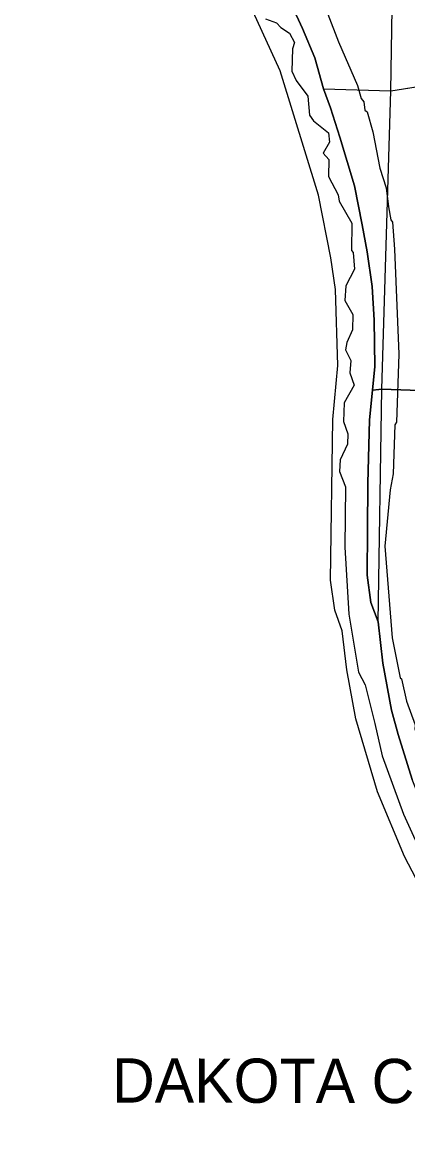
# Model space of a CAD drawing. Extents: x -157.2 to -99.3, y 12.2 to 46.2.
# Drawn here: x -147.848 to -146.803, y 21.191 to 24.227 of the extents above; entities that cross this region are included whole.
import ezdxf

# ---------------------------------------------------------------- set-up
doc = ezdxf.new("R2010")
doc.units = 0
for name, color, linetype in [('tdCoClipBndry', 7, 'Continuous'), ('tdCoCoBndry', 7, 'Continuous'), ('tdCoCoBndryTxt', 7, 'Continuous'), ('tdCoHydroRiver', 7, 'Continuous'), ('tdCoSectLine', 7, 'Continuous'), ('tdCoSectLinePart', 7, 'Continuous'), ('tdCoStBndry', 7, 'Continuous'), ('tdCoStBndryPart', 7, 'Continuous'), ('tdCoTwpBndry', 7, 'Continuous'), ('tdCoTwpBndryShd', 7, 'Continuous')]:
    doc.layers.add(name, color=color, linetype=linetype)

msp = doc.modelspace()

# ---------------------------------------------------------------- linework, layer by layer
at = {"layer": 'tdCoClipBndry'}
msp.add_lwpolyline([(-145.817, 21.0314), (-146.2268, 21.2848), (-146.2839, 21.3266), (-146.4611, 21.4845), (-146.5453, 21.5662), (-146.6561, 21.702), (-146.7589, 21.8639), (-146.8111, 21.9641), (-146.8849, 22.1401), (-146.9435, 22.3377), (-146.9681, 22.4706), (-146.9803, 22.5766), (-147.0007, 22.6324), (-147.0119, 22.7144), (-147.0061, 23.1502), (-146.9918, 23.2968), (-146.9986, 23.5021), (-147.0107, 23.5882), (-147.0443, 23.7589), (-147.1482, 24.0956), (-147.2706, 24.3631)], dxfattribs=at)
at = {"layer": 'tdCoCoBndry'}
msp.add_lwpolyline([(-146.7907, 22.1736), (-146.8285, 22.2952), (-146.8463, 22.3609), (-146.8697, 22.4886), (-146.8825, 22.6008), (-146.903, 22.6534), (-146.9127, 22.7275), (-146.9118, 22.8503), (-146.9109, 22.9761), (-146.9061, 23.1487), (-146.8977, 23.2298), (-146.8917, 23.2934), (-146.8931, 23.4198), (-146.8988, 23.5107), (-146.9121, 23.6048), (-146.9265, 23.6779), (-146.9472, 23.7834), (-146.9864, 23.9154), (-147.012, 23.9956), (-147.0312, 24.0467), (-147.0546, 24.1312), (-147.088, 24.2108), (-147.1491, 24.3442)], dxfattribs=at)
at = {"layer": 'tdCoHydroRiver'}
for points in [[(-147.201, 24.5448), (-147.1535, 24.4833), (-147.0579, 24.3191), (-147.0192, 24.2499), (-146.9901, 24.1747), (-146.9387, 24.0561), (-146.9288, 24.021), (-146.9212, 24.0113), (-146.9188, 23.9891), (-146.9126, 23.9842), (-146.8971, 23.93), (-146.8782, 23.8314), (-146.861, 23.7787), (-146.8548, 23.7264), (-146.8481, 23.6914), (-146.8435, 23.685), (-146.838, 23.6122), (-146.8269, 23.3275), (-146.8329, 23.1429)], [(-147.1885, 24.2365), (-147.1588, 24.2261), (-147.1466, 24.213), (-147.1235, 24.1981), (-147.1101, 24.1724), (-147.1154, 24.1552), (-147.1174, 24.0952), (-147.1056, 24.0695), (-147.0738, 24.0274), (-147.0692, 23.9752), (-147.0586, 23.9606), (-147.0171, 23.9276), (-147.0148, 23.9023), (-147.0315, 23.8728), (-147.0163, 23.855), (-147.0178, 23.8092), (-146.9911, 23.7594), (-146.9885, 23.7419), (-146.9541, 23.6823), (-146.955, 23.6081), (-146.9504, 23.6032), (-146.9472, 23.5573), (-146.9708, 23.5123), (-146.9736, 23.4729), (-146.9512, 23.4343), (-146.9526, 23.3933), (-146.9679, 23.359), (-146.9717, 23.3386), (-146.9569, 23.3097), (-146.9596, 23.2766), (-146.948, 23.2431), (-146.9749, 23.195), (-146.9765, 23.1445), (-146.965, 23.111), (-146.9659, 23.0826), (-146.9862, 23.0406), (-146.9873, 23.0091), (-146.9713, 22.9675), (-146.9735, 22.8033), (-146.9621, 22.6213), (-146.9357, 22.4641)], [(-146.8329, 23.1429), (-146.8379, 23.1352), (-146.8423, 23.0027), (-146.85, 22.9587), (-146.8645, 22.806), (-146.8443, 22.5574), (-146.8226, 22.4493), (-146.8195, 22.446), (-146.8057, 22.3855), (-146.7826, 22.3216), (-146.783, 22.309), (-146.7784, 22.3057), (-146.7672, 22.2595), (-146.6163, 21.9544), (-146.5789, 21.8916), (-146.3915, 21.6358), (-146.3473, 21.5886), (-146.2967, 21.5427), (-146.252, 21.5096), (-146.0694, 21.3504), (-145.7018, 21.1044)], [(-146.9357, 22.4641), (-146.9179, 22.4303), (-146.8914, 22.3252), (-146.8721, 22.2377), (-146.8142, 22.0794), (-146.7494, 21.9383), (-146.6351, 21.764), (-146.5515, 21.6664), (-146.347, 21.4527), (-146.2458, 21.3641), (-146.1025, 21.2583), (-145.8594, 21.1128)]]:
    msp.add_lwpolyline(points, dxfattribs=at)
at = {"layer": 'tdCoSectLine'}
for points in [[(-147.8482, 25.1108), (-147.7708, 25.0498), (-147.7104, 25.0029), (-147.6266, 24.9312), (-147.547, 24.8525), (-147.4738, 24.7758), (-147.3843, 24.6807), (-147.3254, 24.6126), (-147.2877, 24.5643), (-147.2238, 24.4756), (-147.1825, 24.411), (-147.1491, 24.3442), (-147.088, 24.2108), (-147.0546, 24.1312), (-147.0312, 24.0467)], [(-146.8481, 24.0419), (-146.8319, 25.0427)], [(-146.8481, 24.0419), (-145.853, 24.1993)], [(-147.0312, 24.0467), (-146.8481, 24.0419)], [(-147.0312, 24.0467), (-147.012, 23.9956), (-146.9864, 23.9154), (-146.9472, 23.7834), (-146.9265, 23.6779), (-146.9121, 23.6048), (-146.8988, 23.5107), (-146.8931, 23.4198), (-146.8917, 23.2934), (-146.8977, 23.2298)], [(-146.8729, 23.2324), (-146.8481, 24.0419)], [(-146.8977, 23.2298), (-146.9061, 23.1487), (-146.9109, 22.9761), (-146.9118, 22.8503), (-146.9127, 22.7275), (-146.903, 22.6534), (-146.8825, 22.6008)], [(-146.8977, 23.2298), (-146.8729, 23.2324)], [(-146.8825, 22.6008), (-146.8729, 23.2324)], [(-146.8729, 23.2324), (-145.8715, 23.197)], [(-146.8825, 22.6008), (-146.8697, 22.4886), (-146.8463, 22.3609), (-146.8285, 22.2952), (-146.7907, 22.1736)]]:
    msp.add_lwpolyline(points, dxfattribs=at)
at = {"layer": 'tdCoSectLinePart'}
for points in [[(-147.8482, 25.1108), (-147.7708, 25.0498), (-147.7104, 25.0029), (-147.6266, 24.9312), (-147.547, 24.8525), (-147.4738, 24.7758), (-147.3843, 24.6807), (-147.3254, 24.6126), (-147.2877, 24.5643), (-147.2238, 24.4756), (-147.1825, 24.411), (-147.1491, 24.3442), (-147.088, 24.2108), (-147.0546, 24.1312), (-147.0312, 24.0467)], [(-146.8481, 24.0419), (-146.8319, 25.0427)], [(-146.8481, 24.0419), (-146.3861, 24.115)], [(-147.0312, 24.0467), (-146.8481, 24.0419)], [(-147.0312, 24.0467), (-147.012, 23.9956), (-146.9864, 23.9154), (-146.9472, 23.7834), (-146.9265, 23.6779), (-146.9121, 23.6048), (-146.8988, 23.5107), (-146.8931, 23.4198), (-146.8917, 23.2934), (-146.8977, 23.2298)], [(-146.8729, 23.2324), (-146.8481, 24.0419)], [(-146.8977, 23.2298), (-146.9061, 23.1487), (-146.9109, 22.9761), (-146.9118, 22.8503), (-146.9127, 22.7275), (-146.903, 22.6534), (-146.8825, 22.6008)], [(-146.8977, 23.2298), (-146.8729, 23.2324)], [(-146.8825, 22.6008), (-146.8729, 23.2324)], [(-146.8729, 23.2324), (-145.8715, 23.197)], [(-146.8825, 22.6008), (-146.8697, 22.4886), (-146.8463, 22.3609), (-146.8285, 22.2952), (-146.7907, 22.1736)]]:
    msp.add_lwpolyline(points, dxfattribs=at)
at = {"layer": 'tdCoStBndry'}
msp.add_lwpolyline([(-147.1491, 24.3442), (-147.088, 24.2108), (-147.0546, 24.1312), (-147.0312, 24.0467), (-147.012, 23.9956), (-146.9864, 23.9154), (-146.9472, 23.7834), (-146.9265, 23.6779), (-146.9121, 23.6048), (-146.8988, 23.5107), (-146.8931, 23.4198), (-146.8917, 23.2934), (-146.8977, 23.2298), (-146.9061, 23.1487), (-146.9109, 22.9761), (-146.9118, 22.8503), (-146.9127, 22.7275), (-146.903, 22.6534), (-146.8825, 22.6008), (-146.8697, 22.4886), (-146.8463, 22.3609), (-146.8285, 22.2952), (-146.7907, 22.1736)], dxfattribs=at)
at = {"layer": 'tdCoStBndryPart'}
msp.add_lwpolyline([(-147.1491, 24.3442), (-147.088, 24.2108), (-147.0546, 24.1312), (-147.0312, 24.0467), (-147.012, 23.9956), (-146.9864, 23.9154), (-146.9472, 23.7834), (-146.9265, 23.6779), (-146.9121, 23.6048), (-146.8988, 23.5107), (-146.8931, 23.4198), (-146.8917, 23.2934), (-146.8977, 23.2298), (-146.9061, 23.1487), (-146.9109, 22.9761), (-146.9118, 22.8503), (-146.9127, 22.7275), (-146.903, 22.6534), (-146.8825, 22.6008), (-146.8697, 22.4886), (-146.8463, 22.3609), (-146.8285, 22.2952), (-146.7907, 22.1736)], dxfattribs=at)
at = {"layer": 'tdCoTwpBndry'}
msp.add_lwpolyline([(-145.8183, 23.1948), (-145.8715, 23.197), (-146.8729, 23.2324), (-146.8972, 23.2298)], dxfattribs=at)
at = {"layer": 'tdCoTwpBndryShd'}
for points in [[(-146.8825, 22.6008), (-146.903, 22.6534), (-146.9127, 22.7275), (-146.9118, 22.8503), (-146.9109, 22.9761), (-146.9061, 23.1487), (-146.8977, 23.2298), (-146.8917, 23.2934), (-146.8931, 23.4198), (-146.8988, 23.5107), (-146.9121, 23.6048), (-146.9265, 23.6779), (-146.9472, 23.7834), (-146.9864, 23.9154), (-147.012, 23.9956), (-147.0312, 24.0467), (-147.0546, 24.1312), (-147.088, 24.2108), (-147.1491, 24.3442)], [(-146.8729, 23.2324), (-145.8715, 23.197), (-144.8712, 23.155), (-143.8725, 23.1409), (-142.8769, 23.1119), (-141.8842, 23.0634), (-140.8917, 23.0263), (-139.9101, 22.9943), (-138.9141, 22.9595), (-137.92, 22.9236), (-137.2834, 22.8964), (-136.9243, 22.8946), (-135.9317, 22.8553), (-134.9318, 22.8156), (-134.4557, 22.7924)], [(-145.8738, 21.1836), (-145.908, 21.203), (-145.9855, 21.2499), (-146.0571, 21.2947), (-146.1195, 21.336), (-146.1683, 21.3658), (-146.2174, 21.4012), (-146.2623, 21.4413), (-146.3066, 21.4808), (-146.3946, 21.5591), (-146.4716, 21.6338), (-146.5301, 21.701), (-146.575, 21.7605), (-146.6345, 21.8521), (-146.6745, 21.9174), (-146.7223, 22.01), (-146.7623, 22.1036), (-146.7907, 22.1736), (-146.8285, 22.2952), (-146.8463, 22.3609), (-146.8697, 22.4886), (-146.8825, 22.6008)]]:
    msp.add_lwpolyline(points, dxfattribs=at)

# ---------------------------------------------------------------- texts
at = {"layer": 'tdCoCoBndryTxt'}
msp.add_text('DAKOTA CO.', height=0.12, rotation=359.8876, dxfattribs=at).set_placement((-147.605, 21.2967))

doc.saveas('drawing.dxf')
